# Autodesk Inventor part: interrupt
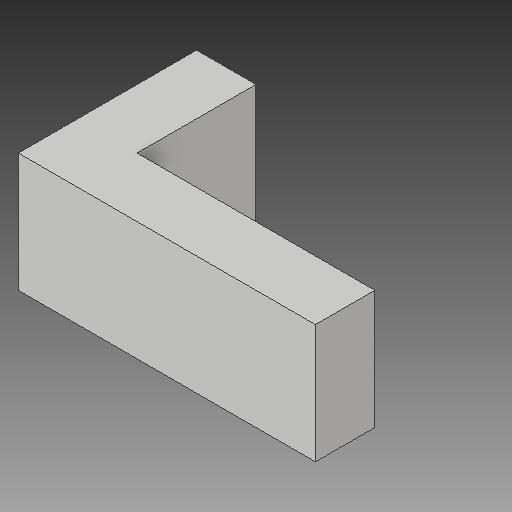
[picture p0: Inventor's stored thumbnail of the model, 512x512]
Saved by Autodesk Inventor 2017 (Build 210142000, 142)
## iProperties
Created: 2020-03
Part Number: interrupt
Material: Generic
Document SubType Name: Modeling
Designer: user
Density: 1 g/cm^3
Appearance: Default
Author: user
Revision Number: ANY
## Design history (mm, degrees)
feature "Boss-Extrude1"
body "Solid1"
